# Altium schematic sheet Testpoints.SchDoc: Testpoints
size 431 x 279 mm
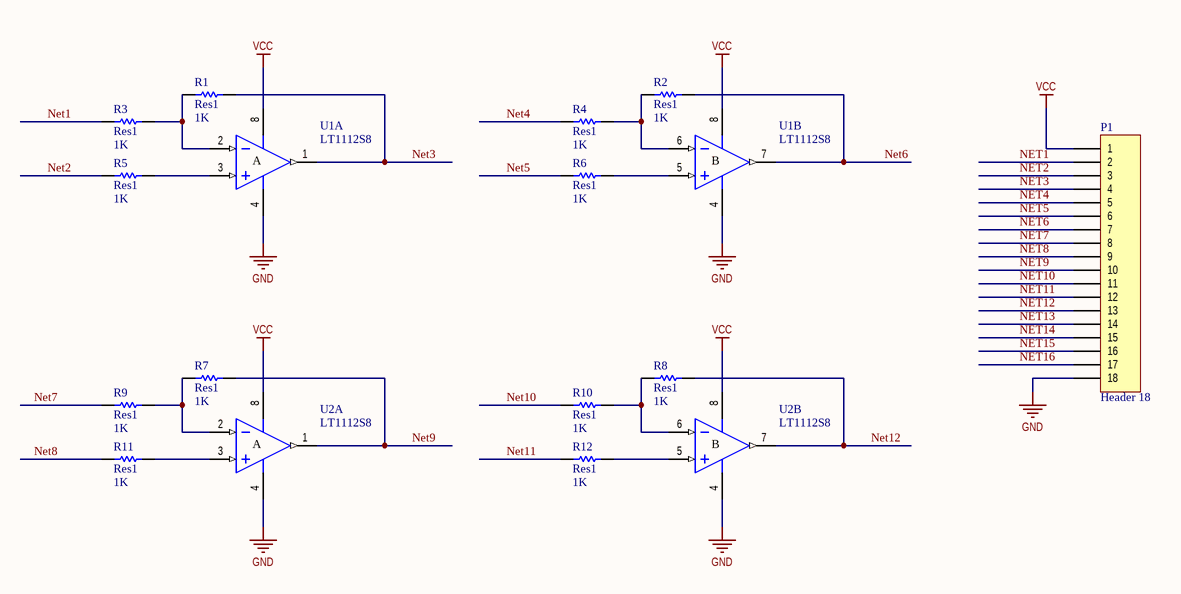
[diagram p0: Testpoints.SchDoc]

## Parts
P1  Header 18  [HDR1X18]
R1  Res1  value 1K  [AXIAL-0.3]
R2  Res1  value 1K  [AXIAL-0.3]
R3  Res1  value 1K  [AXIAL-0.3]
R4  Res1  value 1K  [AXIAL-0.3]
R5  Res1  value 1K  [AXIAL-0.3]
R6  Res1  value 1K  [AXIAL-0.3]
R7  Res1  value 1K  [AXIAL-0.3]
R8  Res1  value 1K  [AXIAL-0.3]
R9  Res1  value 1K  [AXIAL-0.3]
R10  Res1  value 1K  [AXIAL-0.3]
R11  Res1  value 1K  [AXIAL-0.3]
R12  Res1  value 1K  [AXIAL-0.3]
U1  LT1112S8  [S8_N]  (parts A,B of 2)
U2  LT1112S8  [S8_N]  (parts A,B of 2)

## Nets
GND: P1.18 U1.4(V-) U2.4(V-)
VCC: P1.1 U1.8(V+) U2.8(V+)
Net1: P1.2 R3.1
Net2: P1.3 R5.1
Net3: P1.4 R1.2 U1.1(OUT)
Net4: P1.5 R4.1
Net5: P1.6 R6.1
Net6: P1.7 R2.2 U1.7(OUT)
Net7: P1.8 R9.1
Net8: P1.9 R11.1
Net9: P1.10 R7.2 U2.1(OUT)
Net10: P1.11 R10.1
Net11: P1.12 R12.1
Net12: P1.13 R8.2 U2.7(OUT)
NET13: P1.14
NET14: P1.15
NET15: P1.16
NET16: P1.17
NetR1_1: R1.1 R3.2 U1.2(IN-)
NetR2_1: R2.1 R4.2 U1.6(IN-)
NetR5_2: R5.2 U1.3(IN+)
NetR6_2: R6.2 U1.5(IN+)
NetR7_1: R7.1 R9.2 U2.2(IN-)
NetR8_1: R8.1 R10.2 U2.6(IN-)
NetR11_2: R11.2 U2.3(IN+)
NetR12_2: R12.2 U2.5(IN+)

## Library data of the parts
P1 = Header 18: Header, 18-Pin
R1-R12 = Res1: Resistor
U1 U2 = LT1112S8: Dual Low Power Precision, Picoamp Input Operational Amplifier; Note: 462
